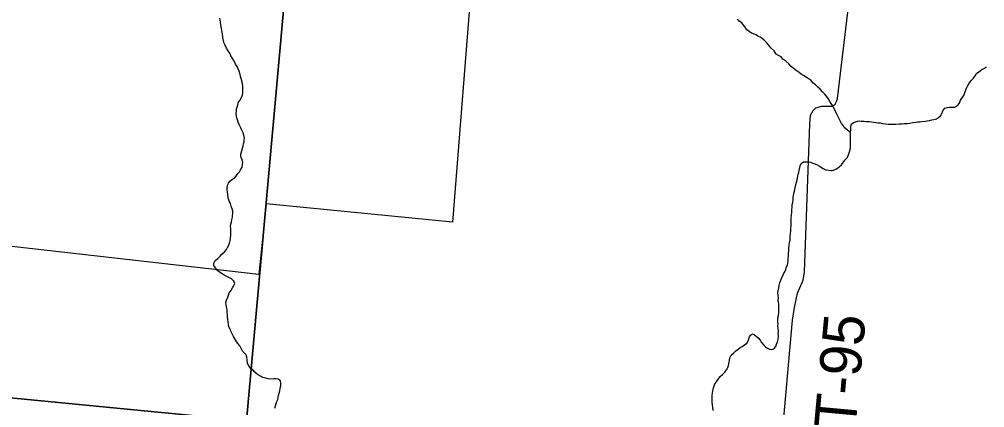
# Model space of a CAD drawing. Extents: x 0 to 1064, y 0 to 440.
# Drawn here: x 273.78 to 294.9, y 251.21 to 259.71 of the extents above; entities that cross this region are included whole.
import ezdxf

# ---------------------------------------------------------------- set-up
doc = ezdxf.new("R2010")
doc.units = 0
for name, color, linetype in [('GM_X_Corporation', 7, 'Continuous'), ('GM_X_Minor_River', 7, 'Continuous'), ('GM_X_Section', 7, 'Continuous'), ('GM_X_Township_Road', 7, 'Continuous'), ('GM_X_Township_Road_Text', 7, 'Continuous')]:
    doc.layers.add(name, color=color, linetype=linetype)

msp = doc.modelspace()

# ---------------------------------------------------------------- linework, layer by layer
at = {"layer": 'GM_X_Corporation'}
msp.add_lwpolyline([(273.343, 265.145), (274.049, 265.025), (274.096, 265.009), (275.204, 264.804), (274.973, 263.074), (274.956, 262.634), (279.782, 262.618), (279.698, 261.6), (283.724, 261.177), (283.257, 255.27), (279.179, 255.674), (279.019, 254.123), (270.461, 255.096)], dxfattribs=at)
at = {"layer": 'GM_X_Minor_River'}
for points in [[(278.514, 258.727), (278.474, 258.807), (278.44, 258.869), (278.411, 258.912), (278.394, 258.955), (278.347, 259.023), (278.313, 259.079), (278.284, 259.147), (278.256, 259.208), (278.251, 259.251), (278.235, 259.312), (278.226, 259.391), (278.21, 259.465), (278.205, 259.513), (278.19, 259.593), (278.179, 259.648), (278.17, 259.739)], [(291.97, 257.237), (291.827, 257.345), (291.804, 257.388), (291.769, 257.431), (291.741, 257.487), (291.718, 257.536), (291.701, 257.579), (291.666, 257.635), (291.621, 257.733), (291.558, 257.845), (291.517, 257.913), (291.477, 257.981), (291.442, 258.03), (291.401, 258.08), (291.354, 258.124), (291.301, 258.181), (291.254, 258.224), (291.2, 258.275), (291.141, 258.325), (291.106, 258.375), (291.017, 258.432), (290.939, 258.483), (290.885, 258.509), (290.844, 258.547), (290.778, 258.591), (290.713, 258.642), (290.672, 258.68), (290.619, 258.736), (290.554, 258.793), (290.488, 258.843), (290.447, 258.893), (290.394, 258.919), (290.34, 258.951), (290.294, 259.025), (290.234, 259.082), (290.17, 259.157), (290.129, 259.206), (290.076, 259.257), (290.034, 259.294), (289.993, 259.32), (289.951, 259.339), (289.897, 259.371), (289.843, 259.391), (289.801, 259.411), (289.747, 259.443), (289.7, 259.481), (289.659, 259.537), (289.63, 259.58), (289.589, 259.636), (289.529, 259.674), (289.494, 259.718)], [(278.314, 253.565), (278.34, 253.625), (278.36, 253.673), (278.374, 253.721), (278.406, 253.769), (278.444, 253.829), (278.464, 253.87), (278.496, 253.924), (278.474, 253.979), (278.42, 254.03), (278.378, 254.049), (278.307, 254.088), (278.265, 254.107), (278.217, 254.139), (278.164, 254.177), (278.116, 254.215), (278.075, 254.271), (278.04, 254.321), (278.036, 254.375), (278.062, 254.429), (278.125, 254.476), (278.175, 254.523), (278.213, 254.57), (278.27, 254.623), (278.314, 254.671), (278.333, 254.712), (278.366, 254.766), (278.379, 254.808), (278.393, 254.869), (278.401, 254.923), (278.409, 254.989), (278.411, 255.038), (278.412, 255.08), (278.408, 255.129), (278.403, 255.172), (278.411, 255.226), (278.425, 255.28), (278.433, 255.323), (278.447, 255.377), (278.448, 255.419), (278.455, 255.462), (278.451, 255.51), (278.44, 255.559), (278.418, 255.621), (278.402, 255.676), (278.379, 255.719), (278.368, 255.762), (278.351, 255.805), (278.341, 255.872), (278.337, 255.933), (278.326, 255.976), (278.328, 256.018), (278.336, 256.079), (278.356, 256.127), (278.387, 256.168), (278.444, 256.215), (278.499, 256.244), (278.531, 256.291), (278.563, 256.333), (278.595, 256.374), (278.621, 256.416), (278.653, 256.476), (278.661, 256.53), (278.669, 256.578), (278.659, 256.639), (278.63, 256.707), (278.626, 256.762), (278.64, 256.81), (278.667, 256.888), (278.681, 256.942), (278.688, 256.985), (278.702, 257.027), (278.703, 257.069), (278.705, 257.112), (278.694, 257.173), (278.678, 257.228), (278.649, 257.283), (278.627, 257.333), (278.592, 257.407), (278.57, 257.462), (278.553, 257.511), (278.531, 257.579), (278.528, 257.658), (278.53, 257.712), (278.531, 257.755), (278.558, 257.833), (278.572, 257.887), (278.623, 257.958), (278.663, 258.054), (278.67, 258.109), (278.672, 258.163), (278.674, 258.206), (278.669, 258.254), (278.653, 258.334), (278.638, 258.413), (278.621, 258.462), (278.61, 258.505), (278.588, 258.579), (278.566, 258.628), (278.549, 258.677), (278.514, 258.727)], [(292.118, 257.481), (292.161, 257.486), (292.203, 257.485), (292.264, 257.483), (292.313, 257.475), (292.38, 257.473), (292.428, 257.466), (292.476, 257.458), (292.525, 257.451), (292.573, 257.443), (292.616, 257.442), (292.664, 257.434), (292.731, 257.426), (292.792, 257.418), (292.834, 257.417), (292.901, 257.415), (292.962, 257.413), (293.035, 257.423), (293.09, 257.427), (293.133, 257.432), (293.176, 257.43), (293.218, 257.429), (293.267, 257.44), (293.329, 257.45), (293.39, 257.46), (293.433, 257.465), (293.488, 257.469), (293.53, 257.474), (293.598, 257.484), (293.646, 257.489), (293.696, 257.499), (293.745, 257.51), (293.793, 257.515), (293.849, 257.531), (293.892, 257.56), (293.936, 257.601), (293.968, 257.649), (293.989, 257.709), (294.033, 257.768), (294.082, 257.785), (294.131, 257.79), (294.186, 257.788), (294.247, 257.792), (294.303, 257.821), (294.353, 257.874), (294.374, 257.94), (294.412, 257.993), (294.451, 258.059), (294.471, 258.107), (294.504, 258.203), (294.53, 258.245), (294.556, 258.299), (294.588, 258.34), (294.614, 258.382), (294.658, 258.423), (294.696, 258.477), (294.728, 258.524), (294.778, 258.559), (294.84, 258.612), (294.896, 258.646), (294.94, 258.675)], [(290.381, 253.175), (290.389, 253.229), (290.397, 253.29), (290.399, 253.338), (290.4, 253.387), (290.397, 253.472), (290.392, 253.515), (290.388, 253.557), (290.39, 253.618), (290.385, 253.667), (290.381, 253.728), (290.388, 253.77), (290.397, 253.836), (290.404, 253.885), (290.424, 253.939), (290.445, 253.999), (290.458, 254.041), (290.484, 254.095), (290.504, 254.137), (290.53, 254.184), (290.55, 254.232), (290.563, 254.275), (290.589, 254.328), (290.597, 254.371), (290.604, 254.413), (290.606, 254.474), (290.608, 254.534), (290.61, 254.577), (290.618, 254.643), (290.62, 254.716), (290.628, 254.758), (290.636, 254.831), (290.644, 254.873), (290.645, 254.922), (290.647, 254.964), (290.655, 255.019), (290.663, 255.073), (290.664, 255.128), (290.667, 255.194), (290.668, 255.249), (290.671, 255.316), (290.672, 255.37), (290.68, 255.413), (290.683, 255.491), (290.684, 255.546), (290.692, 255.594), (290.694, 255.655), (290.702, 255.703), (290.71, 255.758), (290.711, 255.8), (290.719, 255.855), (290.726, 255.897), (290.74, 255.951), (290.755, 256.03), (290.769, 256.096), (290.783, 256.144), (290.803, 256.198), (290.818, 256.277), (290.825, 256.319), (290.839, 256.361), (290.846, 256.403), (290.861, 256.464), (290.868, 256.506), (290.888, 256.554), (290.938, 256.589), (290.993, 256.593), (291.041, 256.592), (291.09, 256.584), (291.144, 256.564), (291.186, 256.545), (291.24, 256.525), (291.288, 256.499), (291.33, 256.467), (291.371, 256.442), (291.431, 256.416), (291.492, 256.408), (291.534, 256.4), (291.577, 256.405), (291.664, 256.439), (291.72, 256.48), (291.77, 256.527), (291.808, 256.574), (291.846, 256.627), (291.89, 256.669), (291.916, 256.722), (291.93, 256.765), (291.944, 256.807), (291.958, 256.861), (291.965, 256.915), (291.967, 256.958), (291.969, 257.037), (291.971, 257.079), (291.966, 257.128), (291.968, 257.176), (291.97, 257.237), (291.972, 257.292), (291.973, 257.346), (291.982, 257.407), (292.032, 257.454), (292.075, 257.471), (292.118, 257.481)], [(279.374, 251.195), (279.388, 251.249), (279.402, 251.303), (279.416, 251.345), (279.436, 251.387), (279.443, 251.429), (279.451, 251.472), (279.465, 251.526), (279.478, 251.58), (279.486, 251.635), (279.5, 251.689), (279.502, 251.743), (279.498, 251.798), (279.444, 251.83), (279.396, 251.838), (279.353, 251.839), (279.28, 251.835), (279.225, 251.843), (279.171, 251.857), (279.104, 251.871), (279.057, 251.897), (278.991, 251.935), (278.932, 251.986), (278.891, 252.035), (278.849, 252.067), (278.808, 252.111), (278.774, 252.179), (278.764, 252.258), (278.76, 252.313), (278.743, 252.362), (278.708, 252.405), (278.667, 252.449), (278.632, 252.505), (278.604, 252.561), (278.563, 252.616), (278.516, 252.679), (278.464, 252.765), (278.447, 252.808), (278.413, 252.87), (278.396, 252.925), (278.367, 252.975), (278.357, 253.03), (278.347, 253.091), (278.343, 253.145), (278.338, 253.194), (278.334, 253.237), (278.33, 253.31), (278.325, 253.352), (278.315, 253.414), (278.305, 253.468), (278.3, 253.511), (278.314, 253.565)], [(288.963, 251.148), (288.953, 251.209), (288.948, 251.27), (288.944, 251.319), (288.94, 251.373), (288.941, 251.416), (288.943, 251.464), (288.951, 251.543), (288.959, 251.603), (288.973, 251.646), (288.986, 251.688), (289, 251.73), (289.032, 251.777), (289.077, 251.843), (289.115, 251.89), (289.165, 251.937), (289.215, 251.984), (289.26, 252.044), (289.286, 252.091), (289.3, 252.133), (289.314, 252.206), (289.322, 252.248), (289.329, 252.303), (289.356, 252.356), (289.412, 252.409), (289.456, 252.451), (289.506, 252.491), (289.55, 252.527), (289.599, 252.549), (289.649, 252.584), (289.699, 252.619), (289.731, 252.673), (289.745, 252.715), (289.758, 252.757), (289.778, 252.799), (289.821, 252.822), (289.869, 252.802), (289.947, 252.739), (289.994, 252.689), (290.022, 252.633), (290.069, 252.577), (290.11, 252.54), (290.152, 252.514), (290.194, 252.488), (290.249, 252.481), (290.292, 252.498), (290.336, 252.551), (290.35, 252.599), (290.37, 252.653), (290.384, 252.707), (290.392, 252.78), (290.388, 252.829), (290.39, 252.883), (290.386, 252.944), (290.381, 252.999), (290.383, 253.041), (290.378, 253.084), (290.379, 253.126), (290.381, 253.175)]]:
    msp.add_lwpolyline(points, dxfattribs=at)
at = {"layer": 'GM_X_Section'}
for points in [[(280.582, 271.247), (278.753, 250.922), (277.718, 251.02), (262.096, 252.537), (264.038, 272.108)], [(297.266, 269.783), (295.423, 249.38), (293.94, 249.48), (278.753, 250.922), (280.582, 271.247)], [(261.545, 252.577), (262.096, 252.537), (277.718, 251.02), (276.183, 234.07), (259.813, 235.795)]]:
    msp.add_lwpolyline(points, close=True, dxfattribs=at)
at = {"layer": 'GM_X_Township_Road'}
msp.add_lwpolyline([(290.404, 249.835), (290.697, 253.124), (290.743, 253.401), (290.806, 253.714), (290.932, 254.003), (290.959, 254.185), (291.075, 257.42), (291.093, 257.615), (291.149, 257.715), (291.21, 257.775), (291.343, 257.808), (291.564, 257.81), (291.632, 257.852), (291.662, 257.911), (291.683, 257.979), (291.956, 260.238), (292.789, 270.143), (293.054, 270.127), (293.155, 270.125)], dxfattribs=at)

# ---------------------------------------------------------------- texts
at = {"layer": 'GM_X_Township_Road_Text'}
msp.add_text('T-95', height=0.9091, rotation=84.7102, dxfattribs=at).set_placement((292.074, 250.724))

doc.saveas('drawing.dxf')
